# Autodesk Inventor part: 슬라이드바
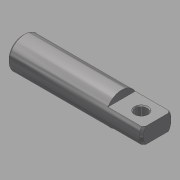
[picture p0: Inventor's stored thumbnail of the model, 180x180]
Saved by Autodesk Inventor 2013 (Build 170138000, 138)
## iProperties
Created: 2015-12
Part Number: 슬라이드바
Material: 스테인리스강
Document SubType Name: Modeling
Designer: mduedu
Density: 8.08 g/cm^3
Author: mduedu
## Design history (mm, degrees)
sketch "스케치1"
  geometry: L1 (-34, 0)-(34, 0); L2 (-34, 0)-(-34, 8); L3 (-34, 8)-(34, 8); L4 (34, 8)-(34, 0); 2 further points
  constraints: 8 end point, 2 perpendicular, 1 coincident, 1 horizontal, 1 midpoint, 1 vertical
  dimensions: "d0" = 68 distance of L2.end L3.end; "d2" = 16 diameter of L3 L1
revolve "회전1" sketch "스케치1" stored, may be unused: angle "d3" = 90 deg
sketch "스케치2"
  geometry: L1 (34, -8)-(34, 8) reference; L2 (0, 0)-(34, 0); L3 (34, 4)-(16, 4); L4 (16, 4)-(16, 8); L5 (16, 8)-(34, 8); L6 (34, 8)-(34, 4); L7 (-34, 8)-(34, 8) reference
  constraints: 10 end point, 2 parallel, 1 collinear, 1 horizontal, 1 midpoint, 1 perpendicular, 1 point on line
  dimensions: "d4" = 18 distance of L4.end L5.end; "d6" = 4 distance between parallel lines of L3 L2
extrude "돌출1" cut sketch "스케치2" stored distance "d8" = 10; taper "d9" = 0 deg
sketch "스케치3"
  geometry: L1 (0, 0)-(0, -13.856) reference; 2 further points
  constraints: 1 horizontal alignment
  dimensions: "d10" = 10 distance from line of point (10, -6.928) L1
hole "구멍1" sketch "스케치3" at (10, -6.928) diameter "d11" = 6; stored, may be unused: countersink angle "d15" = 90 deg, drill point angle "d17" = 118 deg; dims "d12" = 6, "d13" = 4, "d14" = 2, "d16" = 8
chamfer "모따기1" distance "d18" = 0.5; stored, may be unused: second distance "d19" = 2, angle "d20" = 45 deg
chamfer "모따기2" distance "d21" = 1; stored, may be unused: second distance "d22" = 2, angle "d23" = 45 deg
hole "구멍2" diameter "d26" = 4.917; stored, may be unused: countersink angle "d30" = 90 deg, drill point angle "d32" = 118 deg; dims "d24" = 10, "d25" = 10, "d27" = 12, "d28" = 4, "d29" = 2, "d31" = 13
chamfer "모따기3" distance "d33" = 1; stored, may be unused: second distance "d34" = 2, angle "d35" = 45 deg
node "솔리드1"
mirror "대칭1"
